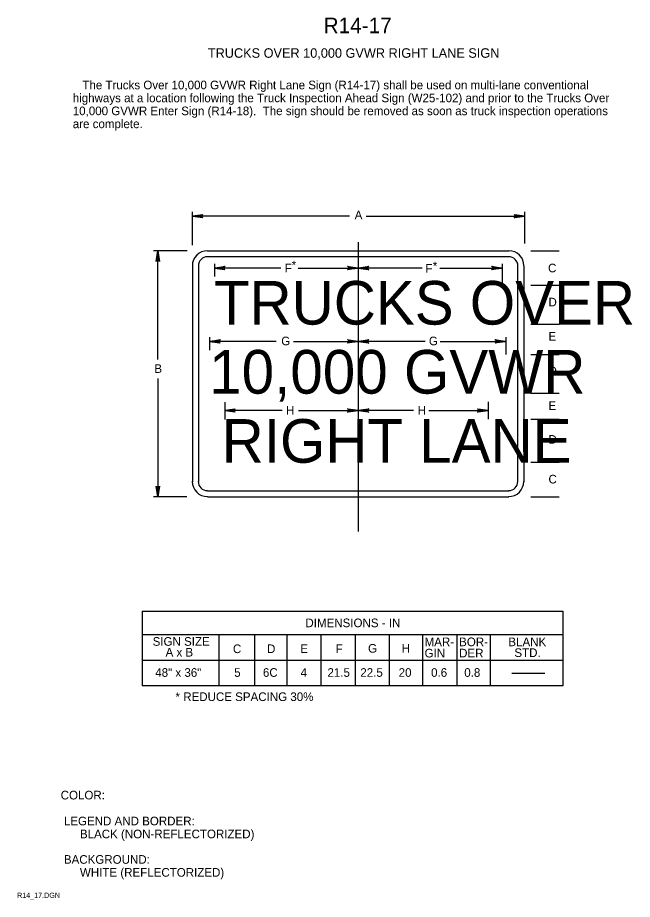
# Model space of a CAD drawing. Extents: x 0.013 to 0.191, y 0.004 to 0.259.
import ezdxf

# ---------------------------------------------------------------- set-up
doc = ezdxf.new("R2010")
doc.units = 0
for name, color, linetype in [('1', 7, 'Continuous'), ('11', 7, 'Continuous'), ('12', 7, 'Continuous'), ('3', 7, 'Continuous')]:
    doc.layers.add(name, color=color, linetype=linetype)

# ---------------------------------------------------------------- blocks, each defined once
blk = doc.blocks.new('RARROW')
at = {"layer": '3'}
for p, q in [((-2.156, 0.285), (-2.2665, 0.384625)), ((-2.2665, 0.384625), (0, 0)), ((0, 0), (-2.2665, -0.379125)), ((-2.156, 0.285), (-2.075625, 0.12075)), ((0, 0), (-2.156, 0.285)), ((-2.14975, -0.2705), (0, 0)), ((-2.075625, 0.12075), (0, 0)), ((0, 0), (-2.074, -0.108)), ((-2.2665, -0.379125), (-2.14975, -0.2705)), ((-2.074, -0.108), (-2.14975, -0.2705))]:
    blk.add_line(p, q, dxfattribs=at)

msp = doc.modelspace()

# ---------------------------------------------------------------- linework, layer by layer
at = {"layer": '11'}
for p, q in [((0.06763, 0.19175), (0.15488, 0.19175)), ((0.06325, 0.18738), (0.06325, 0.12487)), ((0.15925, 0.18738), (0.15925, 0.12487)), ((0.06763, 0.1205), (0.15488, 0.1205))]:
    msp.add_line(p, q, dxfattribs=at)
for centre, radius, start, end in [((0.06763, 0.18738), 0.00438, 90, 180), ((0.15488, 0.18738), 0.00438, 0, 90), ((0.06762, 0.12496), 0.0044, 180, 270), ((0.15482, 0.12496), 0.0044, 270, 0)]:
    msp.add_arc(centre, radius, start, end, dxfattribs=at)
at = {"layer": '3'}
for p, q in [((0.06325, 0.19337), (0.06325, 0.203)), ((0.10875, 0.20175), (0.06325, 0.20175)), ((0.11363, 0.20175), (0.1595, 0.20175)), ((0.1595, 0.19387), (0.1595, 0.203)), ((0.11125, 0.19425), (0.11125, 0.1105)), ((0.06175, 0.19175), (0.052, 0.19175)), ((0.05325, 0.16025), (0.05325, 0.19175)), ((0.16125, 0.19175), (0.1695, 0.19175)), ((0.15488, 0.19), (0.06763, 0.19)), ((0.065, 0.18738), (0.065, 0.12487)), ((0.06963, 0.188), (0.06963, 0.18425)), ((0.08892, 0.18675), (0.06963, 0.18675)), ((0.09388, 0.18675), (0.11125, 0.18675)), ((0.12975, 0.18675), (0.11125, 0.18675)), ((0.13494, 0.18675), (0.153, 0.18675)), ((0.153, 0.188), (0.153, 0.18175)), ((0.1575, 0.12487), (0.1575, 0.18738)), ((0.16125, 0.18175), (0.1695, 0.18175)), ((0.16125, 0.1705), (0.1695, 0.1705)), ((0.06825, 0.16675), (0.06825, 0.163)), ((0.154, 0.16675), (0.154, 0.16175)), ((0.0875, 0.1655), (0.06825, 0.1655)), ((0.0925, 0.1655), (0.11125, 0.1655)), ((0.13062, 0.1655), (0.11125, 0.1655)), ((0.135, 0.1655), (0.154, 0.1655)), ((0.16125, 0.16175), (0.1695, 0.16175)), ((0.05325, 0.15475), (0.05325, 0.1205)), ((0.16125, 0.1505), (0.1695, 0.1505)), ((0.07262, 0.14788), (0.07262, 0.14288)), ((0.14888, 0.148), (0.14888, 0.143)), ((0.08925, 0.1455), (0.07262, 0.1455)), ((0.09401, 0.1455), (0.11125, 0.1455)), ((0.12725, 0.1455), (0.11125, 0.1455)), ((0.13175, 0.1455), (0.14888, 0.1455)), ((0.16125, 0.143), (0.1695, 0.143)), ((0.16125, 0.1305), (0.1695, 0.1305)), ((0.06162, 0.1205), (0.052, 0.1205)), ((0.06763, 0.12225), (0.15488, 0.12225)), ((0.16125, 0.1205), (0.1695, 0.1205)), ((0.04875, 0.08738), (0.1705, 0.08738)), ((0.04875, 0.08738), (0.04875, 0.06575)), ((0.1705, 0.08738), (0.1705, 0.06575)), ((0.1705, 0.0805), (0.04875, 0.0805)), ((0.07091, 0.08048), (0.07091, 0.06573)), ((0.08125, 0.0805), (0.08125, 0.06575)), ((0.09062, 0.0805), (0.09062, 0.06575)), ((0.1005, 0.0805), (0.1005, 0.06575)), ((0.11038, 0.0805), (0.11038, 0.06575)), ((0.12025, 0.0805), (0.12025, 0.06575)), ((0.12987, 0.0805), (0.12987, 0.06575)), ((0.13979, 0.08048), (0.13979, 0.06573)), ((0.1495, 0.0805), (0.1495, 0.06575)), ((0.1705, 0.07312), (0.04875, 0.07312)), ((0.15576, 0.06946), (0.16534, 0.06946)), ((0.1705, 0.06575), (0.04875, 0.06575))]:
    msp.add_line(p, q, dxfattribs=at)
for centre, radius, start, end in [((0.06763, 0.18738), 0.00263, 90, 180), ((0.15488, 0.18738), 0.00263, 0, 90), ((0.06761, 0.12494), 0.00264, 180, 270), ((0.15484, 0.12494), 0.00264, 270, 0)]:
    msp.add_arc(centre, radius, start, end, dxfattribs=at)

# ---------------------------------------------------------------- block references
at = {"layer": '3', "xscale": 0.0013566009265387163, "yscale": 0.0013419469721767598}
for p, rotation in [((0.06325, 0.20175), 180), ((0.05325, 0.19175), 90), ((0.06963, 0.18675), 180), ((0.11125, 0.18675), 180), ((0.06825, 0.1655), 180), ((0.11125, 0.1655), 180), ((0.07262, 0.1455), 180), ((0.11125, 0.1455), 180), ((0.05325, 0.1205), -90)]:
    msp.add_blockref('RARROW', p, dxfattribs=dict(at, rotation=rotation))
for p in [(0.1595, 0.20175), (0.11125, 0.18675), (0.153, 0.18675), (0.11125, 0.1655), (0.154, 0.1655), (0.11125, 0.1455), (0.14888, 0.1455)]:
    msp.add_blockref('RARROW', p, dxfattribs=at)

# ---------------------------------------------------------------- texts
at = {"layer": '1'}
for s, height, p in [('R14-17', 0.0045, (0.10125, 0.25475)), ('TRUCKS OVER 10,000 GVWR RIGHT LANE SIGN', 0.0027503, (0.06775, 0.24763)), ('   The Trucks Over 10,000 GVWR Right Lane Sign (R14-17) shall be used on multi-lane conventional ', 0.0024998, (0.02863, 0.2385)), ('highways at a location following the Truck Inspection Ahead Sign (W25-102) and prior to the Trucks Over ', 0.00249975, (0.02863, 0.23475)), ('10,000 GVWR Enter Sign (R14-18).  The sign should be removed as soon as truck inspection operations ', 0.0024998, (0.02863, 0.231)), ('are complete.', 0.0024998, (0.02863, 0.22725)), ('COLOR:', 0.0025, (0.02513, 0.03288)), (' LEGEND AND BORDER:', 0.0024998, (0.02513, 0.02538)), ('      BLACK (NON-REFLECTORIZED)', 0.0024998, (0.02513, 0.02163)), (' BACKGROUND:', 0.0024998, (0.02513, 0.01425)), ('      WHITE (REFLECTORIZED)', 0.0024998, (0.02513, 0.0105)), ('R14_17.DGN', 0.0015, (0.0125, 0.00438))]:
    msp.add_text(s, height=height, dxfattribs=at).set_placement(p)
at = {"layer": '12'}
for s, height, p in [('TRUCKS OVER', 0.0126248, (0.0695, 0.17037)), ('10,000 GVWR', 0.0126375, (0.06813, 0.15038)), ('RIGHT LANE', 0.012625, (0.07175, 0.13037))]:
    msp.add_text(s, height=height, dxfattribs=at).set_placement(p)
at = {"layer": '3'}
for s, height, p in [('A', 0.0025, (0.11025, 0.20087)), ('F', 0.0025, (0.09, 0.1855)), ('*', 0.0025, (0.092, 0.18638)), ('F', 0.0025, (0.13075, 0.18538)), ('*', 0.0025, (0.13287, 0.18613)), ('C', 0.0025, (0.16625, 0.1855)), ('D', 0.0025, (0.16637, 0.17563)), ('G', 0.0025, (0.089, 0.16437)), ('G', 0.0025, (0.13175, 0.16437)), ('E', 0.0025, (0.16637, 0.16575)), ('B', 0.0025, (0.05225, 0.15638)), ('D', 0.0025, (0.16637, 0.15575)), ('E', 0.0025, (0.16637, 0.14563)), ('H', 0.0025, (0.09037, 0.14425)), ('H', 0.0025, (0.1285, 0.14425)), ('D', 0.0025, (0.16637, 0.13587)), ('C', 0.0025, (0.16637, 0.12437)), ('DIMENSIONS - IN', 0.0024998, (0.09599, 0.08275)), ('SIGN SIZE', 0.0025, (0.05175, 0.07737)), ('MAR-', 0.0025, (0.1305, 0.07725)), ('BOR-', 0.0025, (0.1405, 0.07725)), ('BLANK', 0.0025, (0.15475, 0.07725)), ('A x B', 0.0025, (0.0555, 0.07425)), ('C', 0.0025, (0.075, 0.07525)), ('D', 0.0025, (0.08488, 0.07525)), ('E', 0.0025, (0.0945, 0.07525)), ('F', 0.0025, (0.10475, 0.07525)), ('G', 0.0025, (0.11413, 0.07537)), ('H', 0.0025, (0.12387, 0.07537)), ('STD.', 0.0025, (0.1565, 0.07412)), ('GIN', 0.0025, (0.1305, 0.074)), ('DER', 0.0025, (0.1405, 0.074)), ('48" x 36"', 0.0025, (0.05251, 0.06838)), ('5', 0.0025, (0.07536, 0.06838)), ('6C', 0.0025, (0.08369, 0.06838)), ('4', 0.0025, (0.09459, 0.06838)), ('21.5', 0.0025, (0.10237, 0.06838)), ('22.5', 0.0025, (0.11189, 0.06838)), ('20', 0.0025, (0.12299, 0.06838)), ('0.6', 0.0025, (0.13238, 0.06838)), ('0.8', 0.0025, (0.14199, 0.06838)), ('* REDUCE SPACING 30%', 0.0024998, (0.05838, 0.06137))]:
    msp.add_text(s, height=height, dxfattribs=at).set_placement(p)

doc.saveas('drawing.dxf')
